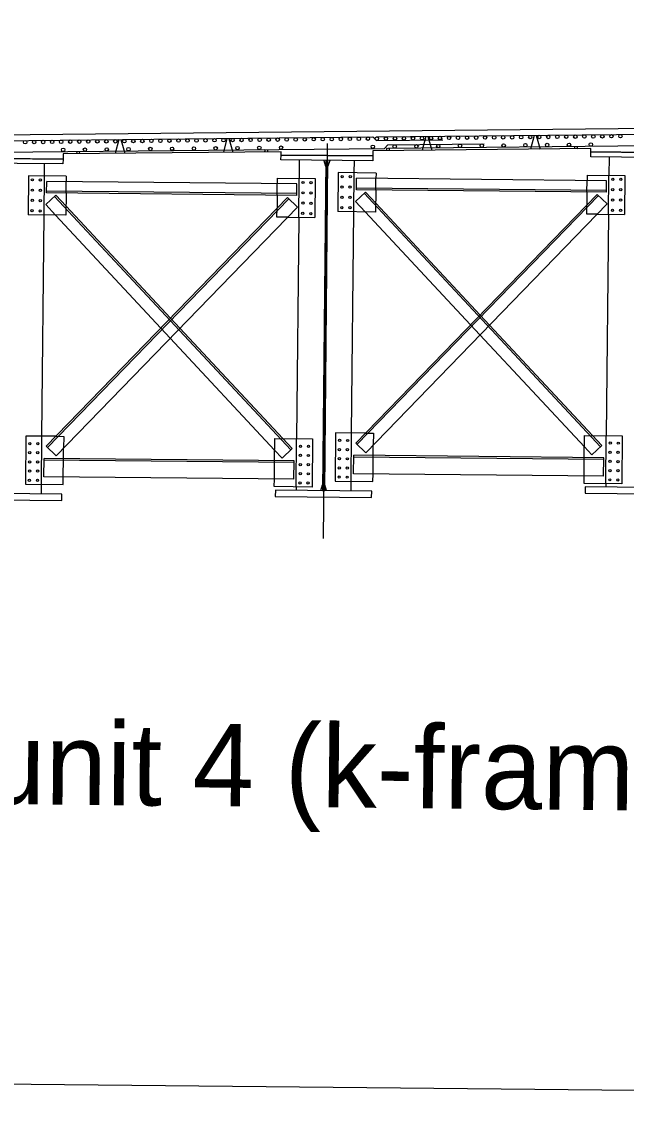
# Model space of a CAD drawing. Extents: x 632066 to 632380, y 378298 to 378447.
# Drawn here: x 632298.44 to 632320.41, y 378297.83 to 378337.25 of the extents above; entities that cross this region are included whole.
import ezdxf

# ---------------------------------------------------------------- set-up
doc = ezdxf.new("R2010")
doc.units = 0
for name, color, linetype in [('B_Boring', 7, 'Continuous'), ('B_Boring Annot', 7, 'Continuous'), ('R_Border_Scale', 7, 'Continuous'), ('R_Proposed Const Limits Cut', 7, 'Continuous'), ('R_Shade Removal', 7, 'Continuous'), ('USACE_Easement', 7, 'Continuous')]:
    doc.layers.add(name, color=color, linetype=linetype)

msp = doc.modelspace()

# ---------------------------------------------------------------- linework, layer by layer
at = {"layer": 'B_Boring'}
for p, q in [((632308.528, 378332.216), (632308.521, 378331.55)), ((632309.423, 378332.207), (632309.484, 378331.999)), ((632309.632, 378332.205), (632309.567, 378331.998)), ((632310.523, 378331.755), (632310.527, 378332.197)), ((632319.779, 378332.33), (632319.773, 378331.663)), ((632299.271, 378331.642), (632299.276, 378332.083)), ((632309.94, 378331.761), (632309.926, 378330.344)), ((632311.315, 378331.747), (632309.94, 378331.761)), ((632298.688, 378331.648), (632298.674, 378330.231)), ((632300.063, 378331.634), (632298.688, 378331.648)), ((632299.349, 378331.026), (632299.353, 378331.443)), ((632308.436, 378331.353), (632299.353, 378331.443)), ((632300.063, 378331.634), (632300.061, 378331.436)), ((632307.729, 378331.558), (632307.727, 378331.36)), ((632307.729, 378331.558), (632309.104, 378331.544)), ((632309.104, 378331.544), (632309.09, 378330.127)), ((632310.6, 378331.139), (632310.604, 378331.556)), ((632319.687, 378331.466), (632310.604, 378331.556)), ((632311.315, 378331.747), (632311.313, 378331.549)), ((632318.981, 378331.671), (632318.979, 378331.473)), ((632318.981, 378331.671), (632320.356, 378331.657)), ((632319.683, 378331.049), (632319.687, 378331.466)), ((632320.356, 378331.657), (632320.342, 378330.24)), ((632308.432, 378330.999), (632299.349, 378331.089)), ((632308.432, 378330.936), (632299.349, 378331.026)), ((632300.057, 378331.019), (632300.049, 378330.217)), ((632308.432, 378330.936), (632308.436, 378331.353)), ((632310.583, 378321.933), (632319.349, 378330.972)), ((632319.683, 378331.049), (632310.6, 378331.139)), ((632319.684, 378331.112), (632310.601, 378331.202)), ((632311.309, 378331.132), (632311.301, 378330.33)), ((632318.975, 378331.056), (632318.97, 378330.581)), ((632319.349, 378330.972), (632319.708, 378330.624)), ((632299.331, 378321.82), (632308.097, 378330.859)), ((632299.376, 378321.776), (632308.142, 378330.815)), ((632307.723, 378330.943), (632307.718, 378330.468)), ((632308.097, 378330.859), (632308.456, 378330.51)), ((632310.628, 378321.89), (632319.394, 378330.928)), ((632310.942, 378321.585), (632319.708, 378330.624)), ((632315.097, 378326.587), (632311.304, 378330.657)), ((632300.049, 378330.217), (632298.674, 378330.231)), ((632299.177, 378322.184), (632299.257, 378330.225)), ((632303.497, 378326.115), (632299.67, 378330.221)), ((632299.69, 378321.472), (632308.456, 378330.51)), ((632303.845, 378326.474), (632300.052, 378330.544)), ((632311.301, 378330.33), (632309.926, 378330.344)), ((632310.429, 378322.297), (632310.509, 378330.338)), ((632314.748, 378326.228), (632310.922, 378330.334)), ((632319.346, 378330.25), (632320.342, 378330.24)), ((632319.759, 378330.246), (632319.679, 378322.205)), ((632308.094, 378330.137), (632309.09, 378330.127)), ((632308.507, 378330.133), (632308.427, 378322.092)), ((632307.925, 378322.097), (632304.187, 378326.108)), ((632318.883, 378321.792), (632315.09, 378325.862)), ((632319.176, 378322.21), (632315.438, 378326.221)), ((632307.631, 378321.679), (632303.838, 378325.749)), ((632309.846, 378322.303), (632309.828, 378320.553)), ((632310.965, 378322.292), (632309.846, 378322.303)), ((632310.931, 378322.292), (632309.846, 378322.303)), ((632298.594, 378322.19), (632298.577, 378320.44)), ((632299.713, 378322.179), (632298.594, 378322.19)), ((632299.679, 378322.179), (632298.594, 378322.19)), ((632307.627, 378321.293), (632307.635, 378322.1)), ((632307.635, 378322.1), (632309.01, 378322.086)), ((632309.01, 378322.086), (632308.993, 378320.336)), ((632310.942, 378321.585), (632310.583, 378321.933)), ((632318.879, 378321.406), (632318.887, 378322.213)), ((632318.887, 378322.213), (632320.262, 378322.199)), ((632320.262, 378322.199), (632320.245, 378320.449)), ((632299.69, 378321.472), (632299.331, 378321.82)), ((632299.961, 378321.369), (632299.965, 378321.755)), ((632299.961, 378321.369), (632299.964, 378321.719)), ((632311.213, 378321.482), (632311.216, 378321.868)), ((632311.213, 378321.482), (632311.216, 378321.832)), ((632299.246, 378320.709), (632299.253, 378321.376)), ((632308.335, 378321.223), (632299.252, 378321.313)), ((632308.336, 378321.285), (632299.253, 378321.376)), ((632308.329, 378320.619), (632308.336, 378321.285)), ((632310.498, 378320.822), (632310.504, 378321.489)), ((632319.587, 378321.399), (632310.504, 378321.489)), ((632319.587, 378321.336), (632310.504, 378321.426)), ((632319.581, 378320.732), (632319.587, 378321.399)), ((632319.581, 378320.732), (632310.498, 378320.822)), ((632311.203, 378320.539), (632311.206, 378320.815)), ((632318.87, 378320.463), (632318.872, 378320.739)), ((632298.577, 378320.44), (632299.952, 378320.426)), ((632299.156, 378320.084), (632299.16, 378320.434)), ((632308.329, 378320.619), (632299.246, 378320.709)), ((632299.952, 378320.426), (632299.954, 378320.702)), ((632307.618, 378320.35), (632307.621, 378320.626)), ((632308.993, 378320.336), (632307.618, 378320.35)), ((632308.41, 378320.342), (632308.408, 378320.217)), ((632309.304, 378320.208), (632309.369, 378320.416)), ((632309.512, 378320.206), (632309.452, 378320.415)), ((632309.828, 378320.553), (632311.203, 378320.539)), ((632310.408, 378320.197), (632310.412, 378320.547)), ((632320.245, 378320.449), (632318.87, 378320.463)), ((632319.661, 378320.455), (632319.66, 378320.33))]:
    msp.add_line(p, q, dxfattribs=at)
for points in [[(632299.942, 378332.077), (632296.609, 378332.11), (632296.611, 378332.287), (632299.944, 378332.254)], [(632311.194, 378332.19), (632307.861, 378332.223), (632307.863, 378332.4), (632311.196, 378332.367)], [(632309.569, 378332.206), (632309.486, 378332.207), (632309.367, 378320.207), (632309.45, 378320.207)], [(632322.446, 378332.303), (632319.113, 378332.336), (632319.114, 378332.513), (632322.448, 378332.48)], [(632318.908, 378320.108), (632322.408, 378320.074), (632322.41, 378320.303), (632318.91, 378320.338)], [(632296.404, 378319.882), (632299.904, 378319.847), (632299.906, 378320.076), (632296.407, 378320.111)], [(632307.656, 378319.995), (632311.156, 378319.96), (632311.158, 378320.19), (632307.658, 378320.224)]]:
    msp.add_lwpolyline(points, close=True, dxfattribs=at)
for centre in [(632298.832, 378331.5), (632299.124, 378331.497), (632308.665, 378331.402), (632308.957, 378331.4), (632310.084, 378331.613), (632310.376, 378331.61), (632319.917, 378331.516), (632320.209, 378331.513), (632298.829, 378331.125), (632299.12, 378331.122), (632308.662, 378331.027), (632308.953, 378331.025), (632310.08, 378331.238), (632310.372, 378331.235), (632319.913, 378331.141), (632320.205, 378331.138), (632298.825, 378330.75), (632299.117, 378330.747), (632308.658, 378330.653), (632308.95, 378330.65), (632310.077, 378330.863), (632310.368, 378330.861), (632319.91, 378330.766), (632320.201, 378330.763), (632298.821, 378330.375), (632299.113, 378330.372), (632308.654, 378330.278), (632308.946, 378330.275), (632310.073, 378330.488), (632310.365, 378330.486), (632319.906, 378330.391), (632320.197, 378330.388), (632298.737, 378321.917), (632299.029, 378321.914), (632309.989, 378322.031), (632310.281, 378322.028), (632319.822, 378321.933), (632320.113, 378321.93), (632298.734, 378321.584), (632299.026, 378321.581), (632308.567, 378321.486), (632308.57, 378321.82), (632308.858, 378321.483), (632308.862, 378321.817), (632309.986, 378321.697), (632310.277, 378321.694), (632319.818, 378321.599), (632320.11, 378321.597), (632298.731, 378321.251), (632299.022, 378321.248), (632308.563, 378321.153), (632308.855, 378321.15), (632309.982, 378321.364), (632310.274, 378321.361), (632319.815, 378321.266), (632320.107, 378321.263), (632298.727, 378320.917), (632299.019, 378320.915), (632308.56, 378320.82), (632308.852, 378320.817), (632309.976, 378320.697), (632309.979, 378321.031), (632310.267, 378320.694), (632310.271, 378321.028), (632319.812, 378320.933), (632320.103, 378320.93), (632298.724, 378320.584), (632299.016, 378320.581), (632308.557, 378320.486), (632308.848, 378320.483), (632319.808, 378320.599), (632320.1, 378320.597)]:
    msp.add_circle(centre, 0.0414, dxfattribs=at)
at = {"layer": 'B_Boring Annot'}
for p, q in [((632325.415, 378333.408), (632285.409, 378333.005)), ((632311.198, 378332.557), (632311.196, 378332.367)), ((632319.116, 378332.636), (632311.198, 378332.557)), ((632319.114, 378332.513), (632319.116, 378332.636)), ((632299.944, 378332.254), (632296.611, 378332.287)), ((632299.946, 378332.443), (632299.944, 378332.254)), ((632307.864, 378332.523), (632299.946, 378332.443)), ((632307.863, 378332.4), (632307.864, 378332.523)), ((632311.196, 378332.367), (632307.863, 378332.4)), ((632322.448, 378332.48), (632319.114, 378332.513))]:
    msp.add_line(p, q, dxfattribs=at)
at = {"layer": 'R_Border_Scale'}
for p, q in [((632284.162, 378332.785), (632311.2, 378333.057)), ((632301.973, 378332.964), (632301.843, 378332.462)), ((632302.047, 378332.965), (632302.185, 378332.466)), ((632305.898, 378333), (632305.769, 378332.502)), ((632305.972, 378333), (632306.11, 378332.505)), ((632311.326, 378332.933), (632311.2, 378333.057)), ((632311.325, 378333.058), (632326.413, 378333.21)), ((632311.326, 378332.933), (632313.743, 378332.957)), ((632313.123, 378333.078), (632312.993, 378332.575)), ((632313.197, 378333.079), (632313.337, 378332.578)), ((632317.061, 378333.114), (632316.932, 378332.614)), ((632317.135, 378333.114), (632317.273, 378332.618)), ((632284.07, 378332.367), (632311.617, 378332.644)), ((632307.285, 378332.6), (632307.263, 378332.517)), ((632307.359, 378332.601), (632307.382, 378332.518)), ((632311.741, 378332.77), (632311.617, 378332.644)), ((632311.701, 378332.645), (632311.68, 378332.561)), ((632311.741, 378332.77), (632315.241, 378332.805)), ((632311.742, 378332.645), (632326.409, 378332.793)), ((632311.776, 378332.646), (632311.799, 378332.563)), ((632318.536, 378332.714), (632318.515, 378332.63)), ((632318.61, 378332.714), (632318.633, 378332.631)), ((632300.45, 378332.532), (632300.428, 378332.448)), ((632300.524, 378332.532), (632300.547, 378332.449))]:
    msp.add_line(p, q, dxfattribs=at)
for centre in [(632298.894, 378332.871), (632299.223, 378332.875), (632299.55, 378332.877), (632299.877, 378332.88), (632300.206, 378332.885), (632300.533, 378332.887), (632300.86, 378332.89), (632301.189, 378332.895), (632301.516, 378332.897), (632301.843, 378332.9), (632302.172, 378332.905), (632302.499, 378332.907), (632302.826, 378332.91), (632303.155, 378332.915), (632303.481, 378332.917), (632303.809, 378332.92), (632304.138, 378332.925), (632304.464, 378332.927), (632304.792, 378332.93), (632305.121, 378332.935), (632305.447, 378332.937), (632305.775, 378332.94), (632306.104, 378332.944), (632306.43, 378332.946), (632306.758, 378332.95), (632307.087, 378332.954), (632307.413, 378332.956), (632307.741, 378332.96), (632308.07, 378332.964), (632308.396, 378332.966), (632308.724, 378332.969), (632309.053, 378332.974), (632309.379, 378332.976), (632309.707, 378332.979), (632310.036, 378332.984), (632310.362, 378332.986), (632310.69, 378332.989), (632311.019, 378332.994), (632311.345, 378332.996), (632311.673, 378332.999), (632312.002, 378333.004), (632312.328, 378333.006), (632312.656, 378333.009), (632312.985, 378333.014), (632313.311, 378333.016), (632313.639, 378333.019), (632313.968, 378333.023), (632314.294, 378333.025), (632314.622, 378333.029), (632314.951, 378333.033), (632315.277, 378333.035), (632315.605, 378333.039), (632315.934, 378333.043), (632316.26, 378333.045), (632316.588, 378333.049), (632316.917, 378333.053), (632317.243, 378333.055), (632317.571, 378333.058), (632317.9, 378333.063), (632318.226, 378333.065), (632318.554, 378333.068), (632318.883, 378333.073), (632319.209, 378333.075), (632319.537, 378333.078), (632319.866, 378333.083), (632320.192, 378333.085), (632298.567, 378332.867), (632299.948, 378332.589), (632300.739, 378332.597), (632301.531, 378332.605), (632302.323, 378332.613), (632303.115, 378332.621), (632303.906, 378332.629), (632304.698, 378332.637), (632305.49, 378332.645), (632306.282, 378332.653), (632307.074, 378332.661), (632307.865, 378332.669), (632311.199, 378332.702), (632311.991, 378332.71), (632312.783, 378332.718), (632313.575, 378332.726), (632314.366, 378332.734), (632315.158, 378332.742), (632315.95, 378332.75), (632316.742, 378332.758), (632317.533, 378332.766), (632318.325, 378332.774), (632319.117, 378332.782)]:
    msp.add_circle(centre, 0.0625, dxfattribs=at)
at = {"layer": 'R_Proposed Const Limits Cut'}
for p, q in [((632310.509, 378330.338), (632310.523, 378331.755)), ((632299.257, 378330.225), (632299.271, 378331.642)), ((632300.057, 378331.019), (632300.061, 378331.436)), ((632307.723, 378330.943), (632307.727, 378331.36)), ((632308.507, 378330.133), (632308.521, 378331.55)), ((632311.309, 378331.132), (632311.313, 378331.549)), ((632318.975, 378331.056), (632318.979, 378331.473)), ((632319.759, 378330.246), (632319.773, 378331.663)), ((632310.933, 378331.055), (632310.567, 378330.714)), ((632319.472, 378321.802), (632310.887, 378331.013)), ((632311.304, 378330.657), (632310.933, 378331.055)), ((632299.681, 378330.942), (632299.316, 378330.601)), ((632299.67, 378330.221), (632299.316, 378330.601)), ((632308.22, 378321.688), (632299.636, 378330.9)), ((632300.052, 378330.544), (632299.681, 378330.942)), ((632310.922, 378330.334), (632310.567, 378330.714)), ((632318.967, 378330.254), (632318.97, 378330.581)), ((632307.715, 378330.141), (632307.718, 378330.468)), ((632319.346, 378330.25), (632318.967, 378330.254)), ((632308.094, 378330.137), (632307.715, 378330.141)), ((632304.187, 378326.108), (632303.845, 378326.474)), ((632315.438, 378326.221), (632315.097, 378326.587)), ((632303.497, 378326.115), (632303.838, 378325.749)), ((632314.748, 378326.228), (632315.09, 378325.862)), ((632310.412, 378320.547), (632310.429, 378322.297)), ((632310.931, 378322.292), (632311.221, 378322.289)), ((632299.16, 378320.434), (632299.177, 378322.184)), ((632299.679, 378322.179), (632299.969, 378322.176)), ((632299.969, 378322.176), (632299.965, 378321.755)), ((632308.266, 378321.731), (632307.925, 378322.097)), ((632308.41, 378320.342), (632308.427, 378322.092)), ((632311.221, 378322.289), (632311.216, 378321.868)), ((632319.517, 378321.844), (632319.176, 378322.21)), ((632319.661, 378320.455), (632319.679, 378322.205)), ((632307.9, 378321.39), (632307.631, 378321.679)), ((632307.9, 378321.39), (632308.266, 378321.731)), ((632319.152, 378321.503), (632318.883, 378321.792)), ((632319.152, 378321.503), (632319.517, 378321.844)), ((632299.954, 378320.702), (632299.961, 378321.369)), ((632307.621, 378320.626), (632307.627, 378321.293)), ((632311.206, 378320.815), (632311.213, 378321.482)), ((632318.872, 378320.739), (632318.879, 378321.406))]:
    msp.add_line(p, q, dxfattribs=at)
at = {"layer": 'R_Shade Removal'}
msp.add_line((632309.534, 378332.822), (632309.391, 378318.472), dxfattribs=at)
at = {"layer": 'USACE_Easement'}
msp.add_lwpolyline([(632266.573, 378373.13), (632378.8, 378372.014), (632378.063, 378297.833), (632265.836, 378298.949)], close=True, dxfattribs=at)

# ---------------------------------------------------------------- texts
msp.add_text('Bridge 01 unit 4 (k-frame no design)', height=3, rotation=359.4304, dxfattribs=at).set_placement((632278.773, 378309.002))

doc.saveas('drawing.dxf')
